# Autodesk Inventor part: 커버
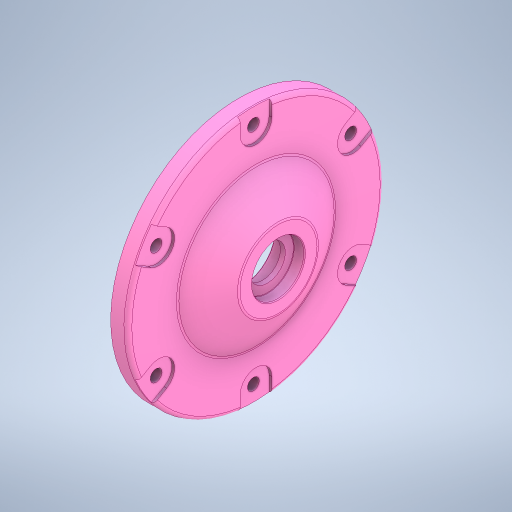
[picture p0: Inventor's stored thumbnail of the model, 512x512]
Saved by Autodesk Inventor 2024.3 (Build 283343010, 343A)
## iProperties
Created: 2025-11
Part Number: 커버
Material: 알루미늄 6061
Document SubType Name: Modeling
Designer: PC2-15
Density: 2.7 g/cm^3
Appearance: 기본값
Author: jhkim
Sending System: Autodesk Inventor 2026
Preprocessor: ST-DEVELOPER v20.1
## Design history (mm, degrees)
node "커버1"
node "솔리드2"
node "솔리드1"
